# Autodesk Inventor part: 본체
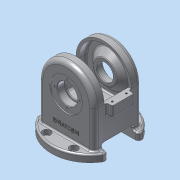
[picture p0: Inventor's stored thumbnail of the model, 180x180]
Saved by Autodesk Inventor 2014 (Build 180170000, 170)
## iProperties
Created: 2024-08
Part Number: 본체
Material: 알루미늄 6061
Document SubType Name: Modeling
Designer: dg
Density: 2.71 g/cm^3
Appearance: 알루미늄 - 평지
Mass: 1115.35 g
Surface Area: 1009.12 cm^2
Volume: 411.568 cm^3
Author: dg
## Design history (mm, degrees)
sketch "스케치1" dims "d0" = 102
  geometry: L1 (-51, 81)-(51, 81); L2 (51, 81)-(51, 0); L3 (51, 0)-(-51, 0); L4 (-51, 0)-(-51, 81); 3 further points
  constraints: 8 end point, 2 coincident, 2 parallel, 1 horizontal, 1 horizontal alignment, 1 midpoint, 1 perpendicular, 2 other
  dimensions: "d1" = 81 distance of L1.end L2.end; "d2" = 102 distance of L2.end L3.end
extrude "돌출1" new body sketch "스케치1" stored distance "d3" = 88; taper "d4" = 0 deg
fillet "모깎기1" dims "d5" = 8
feature "쉘1" dims "d6" = 40, "d7" = 5
sketch "스케치2"
  geometry: L1 (132, 25)-(81, 25); L2 (81, 25)-(81, -25); L3 (81, -25)-(132, -25); L4 (132, -25)-(132, 25); L5 (0, 36)-(0, -36) reference; L6 (81, -36)-(81, -36) reference; L7 (81, -36)-(81, 36) reference; L8 (81, 36)-(81, 36) reference; L9 (81, -36)-(81, 36) reference; L10 (132, -36)-(132, 36) reference; 3 further points
  constraints: 8 end point, 2 midpoint, 2 parallel, 1 horizontal, 1 horizontal alignment, 1 perpendicular
  dimensions: "d8" = 50 distance of L3.end L1.start; "d9" = 132 distance between parallel lines of L5 L4; "d10" = 51 distance of L2.end L3.end
extrude "돌출2" cut sketch "스케치2" stored distance "d11" = 80; taper "d12" = 0 deg
sketch "스케치3"
  geometry: L1 (81, 36)-(81, 44) reference; L2 (81, 44)-(81, 44) reference; L3 (81, 36)-(81, 44) reference; L4 (81, 36)-(81, 36) reference; L5 (81, -36)-(81, -44) reference; L6 (81, -44)-(81, -44) reference; L7 (81, -36)-(81, -44) reference; L8 (81, -36)-(81, -36) reference; L9 (81, 44)-(81, -44); L10 (81, 39)-(124, 39) reference; L11 (124, -39)-(81, -39) reference; L12 (114.5, 39)-(102.5, 27); L13 (102.5, 27)-(81, 27); L14 (127, 25)-(127, 36) reference; L15 (114.5, -39)-(102.5, -27); L16 (102.5, -27)-(81, -27); L17 (114.5, 39)-(81, 39); L18 (114.5, -39)-(81, -39); L19 (81, 27)-(81, 39); L20 (81, -27)-(81, -39); L21 (81, -25)-(81, -25) reference; L22 (81, -36)-(81, -25) reference; L23 (81, -36)-(81, -36) reference; L24 (81, -36)-(81, -25) reference; 1 further point
  constraints: 18 end point, 3 collinear, 3 perpendicular, 2 point on line
  dimensions: "d15" = 12 distance between parallel lines of L10 L13; "d113" = 67 diameter of L12.start L9; "d114" = 12 distance between parallel lines of L11 L16; "d116" = 67 diameter of L15.start L9; "d120" = 45 deg angle of L14 L12; "d121" = 135 deg angle of L9 L15
revolve "회전1" sketch "스케치3" stored, may be unused: angle "d16" = 90 deg
sketch "스케치4"
  geometry: C1 r 16 at (0, 81); A1 r 43 centre (0, 81) between (43, 81) and (-43, 81) reference; 1 further point
  constraints: 1 centre point, 1 coincident
  dimensions: "d17" = 32 diameter of C1
extrude "돌출3" cut sketch "스케치4" stored distance "d18" = 0; taper "d19" = 0 deg
sketch "스케치5"
  geometry: C1 r 16 at (0, 81) reference; C2 r 30 at (0, 81); A1 r 43 centre (0, 81) between (43, 81) and (-43, 81) reference; 1 further point
  constraints: 1 centre point, 1 coincident
  dimensions: "d20" = 60 diameter of C2
extrude "돌출4" cut sketch "스케치5" distance "d21" = 2; taper "d22" = 0 deg
sketch "스케치6"
  geometry: C1 r 30 at (0, 0) reference; A1 r 23 centre (0, 0) between (23, 0) and (0, 23); 3 further points
  constraints: 4 point on circle, 1 centre point, 1 coincident
  dimensions: "d23" = 46 diameter of A1
hole "구멍1" sketch "스케치6" at (23, 0), (0, 23), (-23, 0), (0, -23) diameter "d24" = 3.242; stored, may be unused: countersink angle "d28" = 90 deg, drill point angle "d30" = 118 deg; dims "d25" = 8, "d26" = 4, "d27" = 2, "d29" = 10
sketch "스케치7"
  geometry: L1 (86, 0)-(0, 0) reference; L2 (94, 80)-(94, 8) reference; L3 (0, 88)-(86, 88) reference; L4 (-8, 80)-(-8, 8) reference; C1 r 71 at (43, 44); A1 r 8 centre (0, 8) between (-8, 8) and (0, 0) reference; A2 r 8 centre (86, 8) between (86, 0) and (94, 8) reference; A3 r 8 centre (86, 80) between (94, 80) and (86, 88) reference; A4 r 8 centre (0, 80) between (0, 88) and (-8, 80) reference; 1 further point
  constraints: 1 centre point, 1 coincident
  dimensions: "d31" = 142 diameter of C1
extrude "돌출5" join sketch "스케치7" distance "d32" = 13; taper "d33" = 0 deg
sketch "스케치8"
  geometry: L1 (19, 28)-(0, 28); L2 (0, 28)-(0, -28); L3 (0, -28)-(19, -28); L4 (19, -28)-(19, 28); 3 further points
  constraints: 8 end point, 2 midpoint, 2 parallel, 1 coincident, 1 horizontal, 1 horizontal alignment, 1 perpendicular
  dimensions: "d34" = 19 distance of L2.end L3.end; "d35" = 56 distance of L3.end L1.start
extrude "돌출6" cut sketch "스케치8" stored distance "d36" = 200; taper "d37" = 0 deg
sketch "스케치9"
  geometry: C1 r 11 at (51, 28); 1 further point
  constraints: 1 centre point, 1 coincident
  dimensions: "d38" = 22 diameter of C1
extrude "돌출7" cut sketch "스케치9" distance "d39" = 200; taper "d40" = 0 deg
sketch "스케치10"
  geometry: C1 r 11 at (51, 28) reference; C2 r 14 at (51, 28)
  constraints: 1 centre point, 1 coincident
  dimensions: "d41" = 28 diameter of C2
extrude "돌출8" cut sketch "스케치10" distance "d42" = 18; taper "d43" = 0 deg
sketch "스케치12"
  geometry: L1 (5, 0)-(5, -50) reference; L2 (0, -50)-(5, -50) reference; L3 (-46, -25)-(-46, 69.854); L4 (5, -5)-(15, -5); L5 (15, -5)-(15, -45); L6 (15, -45)-(5, -45); L7 (5, -45)-(5, -5); L8 (-107, -5)-(-107, -45); L9 (-97, -5)-(-107, -5); L10 (-97, 0)-(-97, -50); L11 (-107, -45)-(-97, -45); L12 (-97, -45)-(-97, -5); 1 further point
  constraints: 20 end point, 6 symmetric about line, 2 parallel, 2 perpendicular, 2 point on line, 1 horizontal, 1 horizontal alignment, 1 midpoint
  dimensions: "d52" = 40 distance of L4.end L5.end; "d53" = 61 distance between parallel lines of L3 L5
extrude "돌출9" join sketch "스케치12" distance "d54" = 20; taper "d55" = 0 deg
sketch "스케치13"
  geometry: L1 (-100, -12)-(8, -12); L2 (8, -12)-(8, -38); L3 (8, -38)-(-100, -38); L4 (-100, -38)-(-100, -12); 7 further points
  constraints: 8 end point, 4 coincident, 2 midpoint, 2 parallel, 1 horizontal, 1 horizontal alignment, 1 perpendicular, 1 vertical alignment
  dimensions: "d56" = 108 distance of L2.end L3.end; "d57" = 26 distance of L1.end L2.end
hole "구멍3" sketch "스케치13" at (8, -12), (8, -38), (-100, -38), (-100, -12) diameter "d58" = 3.242; stored, may be unused: countersink angle "d62" = 90 deg, drill point angle "d64" = 118 deg; dims "d59" = 8, "d60" = 4, "d61" = 2, "d63" = 10
sketch "스케치14"
  geometry: C1 r 16 at (0, 0) reference; C2 r 30 at (0, 0) reference; C3 r 18.5 at (0, 0); 1 further point
  constraints: 1 centre point, 1 coincident
  dimensions: "d65" = 37 diameter of C3
extrude "돌출10" cut sketch "스케치14" distance "d66" = 13; taper "d67" = 0 deg
sketch "스케치15"
  geometry: C1 r 16 at (0, 0) reference; C2 r 30 at (0, 0) reference; C3 r 18.5 at (0, 0); 1 further point
  constraints: 1 centre point, 1 coincident
  dimensions: "d68" = 37 diameter of C3
extrude "돌출11" cut sketch "스케치15" distance "d69" = 13; taper "d70" = 0 deg
sketch "스케치16"
  geometry: L1 (18, 11)-(68, 11); L2 (68, 11)-(68, -99); L3 (68, -99)-(18, -99); L4 (18, -99)-(18, 11); A1 r 71 centre (43, -44) between (-22.246, -72) and (108.246, -72) reference; 6 further points
  constraints: 8 end point, 4 coincident, 2 midpoint, 2 parallel, 1 horizontal, 1 horizontal alignment, 1 perpendicular, 1 vertical alignment
  dimensions: "d71" = 50 distance of L2.end L3.end; "d72" = 110 distance of L1.end L2.end
hole "구멍4" sketch "스케치16" at (18, 11), (68, 11), (18, -99), (68, -99) diameter "d73" = 9; stored, may be unused: countersink angle "d77" = 90 deg, drill point angle "d79" = 118 deg; dims "d74" = 8, "d75" = 15, "d76" = 8.8, "d78" = 20
fillet "모깎기2" dims "d80" = 6
fillet "모깎기3" dims "d81" = 0.3
fillet "모깎기4" dims "d82" = 3
fillet "모깎기5" dims "d83" = 3
fillet "모깎기6" dims "d84" = 3
fillet "모깎기7" dims "d85" = 3
chamfer "모따기1" distance "d86" = 1; stored, may be unused: second distance "d87" = 2, angle "d88" = 45 deg
sketch "스케치17"
  geometry: L1 (-35.672, 35)-(35.672, 35); L2 (35.672, 35)-(35.672, 25); L3 (35.672, 25)-(-35.672, 25); L4 (-35.672, 25)-(-35.672, 35); L5 (60.512, 0)-(-60.512, 0) reference; L6 (61.399, 0)-(55.399, 0) reference; 4 further points
  constraints: 2 midpoint, 1 vertical alignment, 2 other
  dimensions: "d92" = 30 vertical distance of L6.start point (0, 30)
feature "엠보싱1" sketch "스케치17" dims "d93" = 0.5, "d94" = 0
sketch "스케치19"
  geometry: C1 r 30 at (0, 0); A1 r 71 centre (0, 0) between (-60.512, -37.138) and (60.512, -37.138) reference
  constraints: 1 centre point, 1 coincident
  dimensions: "d98" = 60 diameter of C1
extrude "돌출13" cut sketch "스케치19" distance "d99" = 22; taper "d100" = 0 deg
fillet "모깎기8" dims "d101" = 3
sketch "스케치20"
  geometry: C1 r 30 at (0, 0) reference; A1 r 23 centre (0, 0) between (23, 0) and (0, 23); 2 further points
  constraints: 4 point on circle, 1 centre point, 1 coincident
  dimensions: "d102" = 46 diameter of A1
hole "구멍5" sketch "스케치20" at (23, 0), (0, 23), (-23, 0), (0, -23) diameter "d103" = 3.242; stored, may be unused: countersink angle "d107" = 90 deg, drill point angle "d109" = 118 deg; dims "d104" = 8, "d105" = 4, "d106" = 2, "d108" = 10
fillet "모깎기9" dims "d110" = 3
chamfer "모따기2" distance "d117" = 1; stored, may be unused: second distance "d118" = 2, angle "d119" = 45 deg
node "솔리드1"
mirror "대칭1"
node "투영된 루프1"
node "투영된 루프2"
node "투영된 루프3"
node "투영된 루프4"
